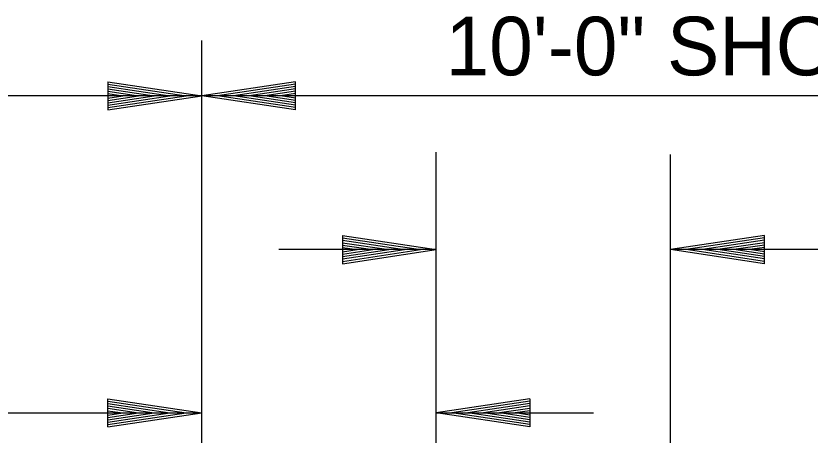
# Model space of a CAD drawing. Extents: x 60325 to 61047, y 53669 to 53767.
# Drawn here: x 60377.66 to 60384.44, y 53691.62 to 53695.2 of the extents above; entities that cross this region are included whole.
import ezdxf

# ---------------------------------------------------------------- set-up
doc = ezdxf.new("R2010")
doc.units = 0
doc.layers.add('R_Border', color=7, linetype='Continuous')
doc.layers.add('R_Border Prem', color=7, linetype='Continuous')

msp = doc.modelspace()

# ---------------------------------------------------------------- linework, layer by layer
at = {"layer": 'R_Border'}
for p, q in [((60379.2467, 53690.5351), (60379.2467, 53694.9869)), ((60378.4467, 53694.6351), (60379.2467, 53694.5151)), ((60378.4467, 53694.6351), (60378.4467, 53694.3951)), ((60378.4467, 53694.6151), (60379.1131, 53694.5151)), ((60378.4467, 53694.5947), (60378.9755, 53694.5151)), ((60378.4467, 53694.5747), (60378.8423, 53694.5151)), ((60379.2467, 53694.5151), (60367.2467, 53694.5151)), ((60378.4467, 53694.5539), (60378.7067, 53694.5151)), ((60378.4467, 53694.5339), (60378.5731, 53694.5151)), ((60378.4467, 53694.3951), (60379.2467, 53694.5151)), ((60378.4467, 53694.4759), (60378.7067, 53694.5151)), ((60378.4467, 53694.4355), (60378.9755, 53694.5151)), ((60378.4467, 53694.4151), (60379.1131, 53694.5151)), ((60378.4467, 53694.4555), (60378.8423, 53694.5151)), ((60378.4467, 53694.4963), (60378.5731, 53694.5151)), ((60381.2467, 53690.4951), (60381.2467, 53694.0347)), ((60378.4467, 53691.9292), (60379.2467, 53691.8092)), ((60378.4467, 53691.6892), (60378.4467, 53691.9292)), ((60382.0467, 53691.9292), (60381.2467, 53691.8092)), ((60382.0467, 53691.9292), (60382.0467, 53691.6892)), ((60378.4467, 53691.9092), (60379.1131, 53691.8092)), ((60378.4467, 53691.8888), (60378.9755, 53691.8092)), ((60378.4467, 53691.8688), (60378.8423, 53691.8092)), ((60382.0467, 53691.9092), (60381.3803, 53691.8092)), ((60382.0467, 53691.8888), (60381.5179, 53691.8092)), ((60382.0467, 53691.8688), (60381.6511, 53691.8092)), ((60375.8999, 53691.8092), (60379.2467, 53691.8092)), ((60378.4467, 53691.8484), (60378.7067, 53691.8092)), ((60378.4467, 53691.828), (60378.5731, 53691.8092)), ((60378.4467, 53691.6892), (60379.2467, 53691.8092)), ((60378.4467, 53691.7704), (60378.7067, 53691.8092)), ((60378.4467, 53691.7296), (60378.9755, 53691.8092)), ((60378.4467, 53691.7092), (60379.1131, 53691.8092)), ((60378.4467, 53691.7496), (60378.8423, 53691.8092)), ((60378.4467, 53691.7904), (60378.5731, 53691.8092)), ((60381.2467, 53691.8092), (60382.5891, 53691.8092)), ((60382.0467, 53691.6892), (60381.2467, 53691.8092)), ((60382.0467, 53691.7092), (60381.3803, 53691.8092)), ((60382.0467, 53691.7296), (60381.5179, 53691.8092)), ((60382.0467, 53691.7496), (60381.6511, 53691.8092)), ((60382.0467, 53691.848), (60381.7867, 53691.8092)), ((60382.0467, 53691.77), (60381.7867, 53691.8092)), ((60382.0467, 53691.828), (60381.9203, 53691.8092)), ((60382.0467, 53691.7904), (60381.9203, 53691.8092))]:
    msp.add_line(p, q, dxfattribs=at)
at = {"layer": 'R_Border Prem'}
for p, q in [((60380.0467, 53694.6351), (60379.2467, 53694.5151)), ((60380.0467, 53694.3951), (60380.0467, 53694.6351)), ((60380.0467, 53694.6151), (60379.3803, 53694.5151)), ((60380.0467, 53694.5947), (60379.5179, 53694.5151)), ((60380.0467, 53694.5747), (60379.6511, 53694.5151)), ((60389.2467, 53694.5151), (60379.2467, 53694.5151)), ((60380.0467, 53694.3951), (60379.2467, 53694.5151)), ((60380.0467, 53694.4151), (60379.3803, 53694.5151)), ((60380.0467, 53694.4355), (60379.5179, 53694.5151)), ((60380.0467, 53694.4555), (60379.6511, 53694.5151)), ((60380.0467, 53694.5543), (60379.7867, 53694.5151)), ((60380.0467, 53694.4763), (60379.7867, 53694.5151)), ((60380.0467, 53694.5339), (60379.9203, 53694.5151)), ((60380.0467, 53694.4963), (60379.9203, 53694.5151)), ((60383.2467, 53690.4951), (60383.2467, 53694.0151)), ((60380.4467, 53693.3225), (60381.2467, 53693.2025)), ((60380.4467, 53693.3225), (60380.4467, 53693.0825)), ((60380.4467, 53693.3025), (60381.1131, 53693.2025)), ((60380.4467, 53693.2821), (60380.9755, 53693.2025)), ((60384.0467, 53693.3225), (60383.2467, 53693.2025)), ((60384.0467, 53693.3025), (60383.3803, 53693.2025)), ((60384.0467, 53693.2821), (60383.5179, 53693.2025)), ((60384.0467, 53693.0825), (60384.0467, 53693.3225)), ((60380.4467, 53693.2621), (60380.8423, 53693.2025)), ((60380.4467, 53693.2413), (60380.7067, 53693.2025)), ((60380.4467, 53693.2213), (60380.5731, 53693.2025)), ((60384.0467, 53693.2621), (60383.6511, 53693.2025)), ((60384.0467, 53693.2417), (60383.7867, 53693.2025)), ((60384.0467, 53693.2213), (60383.9203, 53693.2025)), ((60381.2467, 53693.2025), (60379.9043, 53693.2025)), ((60380.4467, 53693.0825), (60381.2467, 53693.2025)), ((60380.4467, 53693.1633), (60380.7067, 53693.2025)), ((60380.4467, 53693.1229), (60380.9755, 53693.2025)), ((60380.4467, 53693.1025), (60381.1131, 53693.2025)), ((60380.4467, 53693.1429), (60380.8423, 53693.2025)), ((60380.4467, 53693.1837), (60380.5731, 53693.2025)), ((60386.5934, 53693.2025), (60383.2467, 53693.2025)), ((60384.0467, 53693.0825), (60383.2467, 53693.2025)), ((60384.0467, 53693.1025), (60383.3803, 53693.2025)), ((60384.0467, 53693.1229), (60383.5179, 53693.2025)), ((60384.0467, 53693.1429), (60383.6511, 53693.2025)), ((60384.0467, 53693.1637), (60383.7867, 53693.2025)), ((60384.0467, 53693.1837), (60383.9203, 53693.2025))]:
    msp.add_line(p, q, dxfattribs=at)

# ---------------------------------------------------------------- texts
msp.add_text('10\'-0" SHOULDER', height=0.5, dxfattribs=at).set_placement((60381.3276, 53694.6901))

doc.saveas('drawing.dxf')
